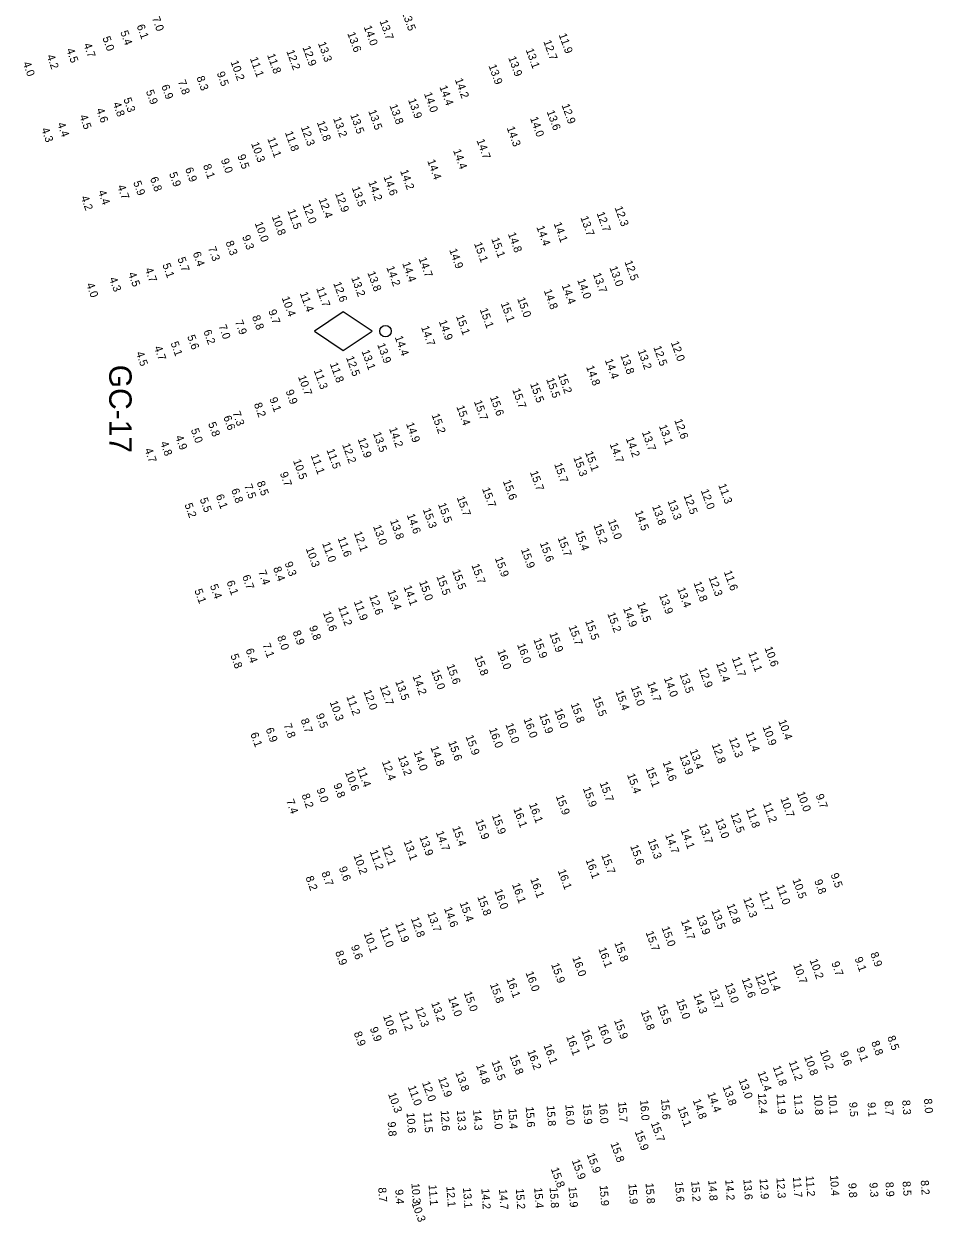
# Model space of a CAD drawing. Extents: x 815385 to 820851, y 582449 to 604245.
# Drawn here: x 820211 to 820779, y 590963 to 591711 of the extents above; entities that cross this region are included whole.
import ezdxf

# ---------------------------------------------------------------- set-up
doc = ezdxf.new("R2010")
doc.units = 0
for name, color, linetype in [('V-CHAN-AIDS', 7, 'Continuous'), ('V-TOPO-SOUN-021309', 7, 'Continuous'), ('V-TOPO-SOUN-112008', 7, 'Continuous'), ('V-TOPO-SOUN-EXCSS', 7, 'Continuous')]:
    doc.layers.add(name, color=color, linetype=linetype)

msp = doc.modelspace()

# ---------------------------------------------------------------- linework, layer by layer
at = {"layer": 'V-CHAN-AIDS'}
msp.add_lwpolyline([(820428.13, 591519.27), (820410.13, 591531.27), (820392.13, 591519.27), (820410.13, 591507.27)], close=True, dxfattribs=at)
msp.add_circle((820436.53, 591519.27), 3.6, dxfattribs=at)

# ---------------------------------------------------------------- texts
msp.add_text('GC-17', height=14, rotation=270, dxfattribs=at).set_placement((820263.84, 591498.29))
at = {"layer": 'V-TOPO-SOUN-021309'}
for s, rotation, p in [('12.0 ', 289.902, (820614.81, 591512.17)), ('13.8 ', 289.902, (820583.24, 591504.04)), ('13.2 ', 289.902, (820594.08, 591507.01)), ('12.5 ', 289.902, (820603.84, 591509.24)), ('14.8 ', 289.902, (820561.86, 591496.92)), ('14.4 ', 289.902, (820573.54, 591501.13)), ('15.5 ', 289.902, (820536.88, 591489.21)), ('15.2 ', 289.902, (820544.23, 591491.95)), ('15.7 ', 289.902, (820515.7, 591482.65)), ('15.5 ', 289.902, (820526.8, 591486.31)), ('15.7 ', 289.902, (820491.72, 591475.26)), ('15.6 ', 289.902, (820501.73, 591478.04)), ('15.2 ', 289.902, (820465.28, 591466.89)), ('15.4 ', 289.902, (820480.77, 591472.03)), ('14.9 ', 289.902, (820449.3, 591461.4)), ('13.1 ', 289.902, (820607.38, 591459.95)), ('12.6 ', 289.902, (820616.96, 591463.57)), ('12.9 ', 289.902, (820419.06, 591451.8)), ('13.5 ', 289.902, (820428.66, 591455.39)), ('14.2 ', 289.902, (820438.68, 591458.34)), ('14.2 ', 289.902, (820586.66, 591452.22)), ('13.7 ', 289.902, (820596.73, 591456.09)), ('11.5 ', 289.902, (820399.59, 591444.97)), ('12.2 ', 289.902, (820409.36, 591448.31)), ('14.7 ', 289.902, (820576.6, 591448.68)), ('10.5 ', 289.902, (820378.66, 591438.31)), ('11.1 ', 289.902, (820389.7, 591441.61)), ('15.3 ', 289.902, (820553.86, 591440.22)), ('15.1 ', 289.902, (820561.19, 591443.41)), ('9.7', 289.902, (820370.41, 591430.4)), ('15.7 ', 289.902, (820526.75, 591431.15)), ('15.7 ', 289.902, (820541.86, 591436.16)), ('7.5', 289.902, (820348.12, 591422.78)), ('8.5', 289.902, (820355.98, 591424.68)), ('15.6 ', 289.902, (820509.83, 591425.46)), ('11.3 ', 289.902, (820644.45, 591423.09)), ('5.5', 289.902, (820320.34, 591414.25)), ('6.1', 289.902, (820330.36, 591416.43)), ('6.8', 289.902, (820339.95, 591420.05)), ('15.7 ', 289.902, (820480.99, 591415.29)), ('15.7 ', 289.902, (820496.81, 591420.78)), ('12.5 ', 289.902, (820622.75, 591416.52)), ('12.0 ', 289.902, (820633.52, 591419.66)), ('5.2', 289.902, (820310.81, 591410.89)), ('15.3 ', 289.902, (820459.77, 591407.77)), ('15.5 ', 289.902, (820469.28, 591411.11)), ('14.5 ', 289.902, (820592.34, 591406.28)), ('13.8 ', 289.902, (820603.09, 591409.78)), ('13.3 ', 289.902, (820612.76, 591413.04)), ('13.8 ', 289.902, (820439.26, 591400.79)), ('14.6 ', 289.902, (820449.76, 591404.34)), ('15.0 ', 289.902, (820575.49, 591400.81)), ('12.1 ', 289.902, (820416.71, 591393.27)), ('13.0 ', 289.902, (820428.7, 591397.25)), ('15.4 ', 289.902, (820555.04, 591393.8)), ('15.2 ', 289.902, (820566.46, 591398)), ('11.0 ', 289.902, (820396.84, 591386.62)), ('11.6 ', 289.902, (820406.54, 591389.9)), ('15.6 ', 289.902, (820532.93, 591386.81)), ('15.7 ', 289.902, (820544.05, 591390.1)), ('10.3 ', 289.902, (820386.6, 591383.39)), ('15.9 ', 289.902, (820504.81, 591377.37)), ('15.9 ', 289.902, (820521.1, 591382.79)), ('7.4', 289.902, (820356.87, 591368.94)), ('8.4', 289.902, (820366.21, 591371.16)), ('9.3', 289.902, (820373.37, 591374.32)), ('15.5 ', 289.902, (820478.1, 591369.54)), ('15.7 ', 289.902, (820490.17, 591373.01)), ('11.6 ', 289.902, (820647.94, 591368.83)), ('6.1', 289.902, (820337.06, 591362.53)), ('6.7', 289.902, (820346.86, 591366.02)), ('15.0 ', 289.902, (820457.42, 591362.57)), ('15.5 ', 289.902, (820468.28, 591365.99)), ('12.8 ', 289.902, (820628.99, 591361.93)), ('12.3 ', 289.902, (820638.41, 591365.29)), ('5.1', 289.902, (820316.98, 591357.3)), ('5.4', 289.902, (820326.69, 591360.21)), ('13.4 ', 289.902, (820437.67, 591356.79)), ('14.1 ', 289.902, (820447.76, 591359.48)), ('13.9 ', 289.902, (820607.47, 591354.19)), ('13.4 ', 289.902, (820618.8, 591358.24)), ('11.2 ', 289.902, (820406.87, 591346.76)), ('11.9 ', 289.902, (820416.63, 591350.17)), ('12.6 ', 289.902, (820426.23, 591353.68)), ('14.5 ', 289.902, (820593.67, 591349.05)), ('10.6 ', 289.902, (820397.35, 591343.34)), ('15.2 ', 289.902, (820575.11, 591342.73)), ('14.9 ', 289.902, (820584.96, 591346.04)), ('8.9', 289.902, (820378.42, 591331.33)), ('9.8', 289.902, (820388.67, 591334.32)), ('15.7 ', 289.902, (820550.93, 591334.6)), ('15.5 ', 289.902, (820561.25, 591337.98)), ('7.1', 289.902, (820359.52, 591323.38)), ('8.0', 289.902, (820368.7, 591328.16)), ('15.9 ', 289.902, (820528.88, 591326.55)), ('15.9 ', 289.902, (820538.83, 591330.29)), ('5.8', 289.902, (820339.49, 591316.66)), ('6.4', 289.902, (820348.99, 591320.09)), ('16.0 ', 289.902, (820506.32, 591319.51)), ('16.0 ', 289.902, (820518.72, 591323.28)), ('11.1 ', 289.902, (820663.22, 591318.15)), ('10.6 ', 289.902, (820673.37, 591321.32)), ('15.6 ', 289.902, (820474.59, 591310.29)), ('15.8 ', 289.902, (820492.03, 591315.72)), ('12.4 ', 289.902, (820643.08, 591311.72)), ('11.7 ', 289.902, (820652.93, 591314.93)), ('14.2 ', 289.902, (820453.36, 591303.6)), ('15.0 ', 289.902, (820464.98, 591306.99)), ('14.0 ', 289.902, (820610.48, 591302.34)), ('13.5 ', 289.902, (820620.25, 591304.74)), ('12.9 ', 289.902, (820632.26, 591308.13)), ('12.0 ', 289.902, (820422.67, 591294.24)), ('12.7 ', 289.902, (820432.78, 591297.15)), ('13.5 ', 289.902, (820442.54, 591300.28)), ('15.4 ', 289.902, (820580.17, 591293.96)), ('15.0 ', 289.902, (820589.84, 591296.76)), ('14.7 ', 289.902, (820599.96, 591299.39)), ('10.3 ', 289.902, (820401.56, 591287.41)), ('11.2 ', 289.902, (820411.96, 591290.89)), ('15.5 ', 289.902, (820565.91, 591290.23)), ('9.5', 289.902, (820392.93, 591279.44)), ('15.9 ', 289.902, (820532.5, 591279.43)), ('16.0 ', 289.902, (820541.96, 591282.68)), ('15.8 ', 289.902, (820552.22, 591286.21)), ('7.8', 289.902, (820372.74, 591273.19)), ('8.7', 289.902, (820383.42, 591276.33)), ('16.0 ', 289.902, (820511.4, 591273.47)), ('16.0 ', 289.902, (820522.71, 591276.78)), ('10.9 ', 289.902, (820672.13, 591271.94)), ('10.4 ', 289.902, (820681.98, 591275.63)), ('6.1', 289.902, (820351.95, 591267.61)), ('6.9', 289.902, (820361.52, 591270.58)), ('15.9 ', 289.902, (820486.5, 591266.03)), ('16.0 ', 289.902, (820501.15, 591270.52)), ('12.3 ', 289.902, (820651.15, 591264.51)), ('11.4 ', 289.902, (820661.59, 591268.13)), ('14.8 ', 289.902, (820464.55, 591259.11)), ('15.6 ', 289.902, (820475.6, 591262.47)), ('13.4 ', 289.902, (820626.55, 591257.2)), ('12.8 ', 289.902, (820640.4, 591260.77)), ('12.4 ', 289.902, (820434.17, 591250.17)), ('13.2 ', 289.902, (820444.21, 591253.21)), ('14.0 ', 289.902, (820454.03, 591256.25)), ('14.6 ', 289.902, (820609.67, 591249.75)), ('13.9 ', 289.902, (820620.17, 591253.77)), ('10.6 ', 289.902, (820411.17, 591243.58)), ('11.4 ', 289.902, (820418.61, 591246.09)), ('15.4 ', 289.902, (820587.43, 591242.03)), ('15.1 ', 289.902, (820599.15, 591246.02)), ('9.8', 289.902, (820403.85, 591235.83)), ('15.7 ', 289.902, (820570.31, 591236.89)), ('8.2', 289.902, (820383.98, 591229.37)), ('9.0', 289.902, (820393.34, 591232.89)), ('15.9 ', 289.902, (820542.93, 591228.65)), ('15.9 ', 289.902, (820559.81, 591233.55)), ('10.7 ', 289.902, (820683.29, 591227.14)), ('10.0 ', 289.902, (820693.62, 591230.68)), ('9.7', 289.902, (820705.31, 591229.14)), ('7.4', 289.902, (820374.36, 591225.83)), ('16.1 ', 289.902, (820516.33, 591220.72)), ('16.1 ', 289.902, (820526.13, 591223.64)), ('11.8 ', 289.902, (820661.76, 591220.52)), ('11.2 ', 289.902, (820672.39, 591223.89)), ('15.9 ', 289.902, (820492.58, 591213.33)), ('15.9 ', 289.902, (820502.98, 591216.56)), ('13.0 ', 289.902, (820642.58, 591213.96)), ('12.5 ', 289.902, (820652.09, 591217.46)), ('14.7 ', 289.902, (820467.93, 591206.09)), ('15.4 ', 289.902, (820478.16, 591209.07)), ('14.7 ', 289.902, (820611.23, 591204.42)), ('14.1 ', 289.902, (820620.98, 591207.47)), ('13.7 ', 289.902, (820632.33, 591210.65)), ('12.1 ', 289.902, (820434.25, 591197.15)), ('13.1 ', 289.902, (820447.75, 591200.28)), ('13.9 ', 289.902, (820457.64, 591203.09)), ('15.6 ', 289.902, (820589.42, 591197.43)), ('15.3 ', 289.902, (820600.38, 591201.12)), ('10.2 ', 289.902, (820416.4, 591191.54)), ('11.2 ', 289.902, (820426.59, 591194.24)), ('15.7 ', 289.902, (820571.33, 591191.75)), ('9.6', 289.902, (820407.3, 591183.79)), ('16.1 ', 289.902, (820544.12, 591182.07)), ('16.1 ', 289.902, (820561.57, 591188.81)), ('8.2', 289.902, (820386.48, 591177.89)), ('8.7', 289.902, (820396.39, 591180.79)), ('16.1 ', 289.902, (820526.94, 591176.82)), ('10.5 ', 289.902, (820690.85, 591176.34)), ('9.8', 289.902, (820704.45, 591175.69)), ('9.5', 289.902, (820714.68, 591179.65)), ('16.0 ', 289.902, (820504.47, 591169.72)), ('16.1 ', 289.902, (820515.54, 591173.49)), ('11.7 ', 289.902, (820669.96, 591168.47)), ('11.0 ', 289.902, (820680.69, 591172.55)), ('15.4 ', 289.902, (820482.79, 591161.91)), ('15.8 ', 289.902, (820493.81, 591165.71)), ('12.8 ', 289.902, (820649.71, 591160.64)), ('12.3 ', 289.902, (820660.07, 591164.51)), ('12.8 ', 289.902, (820452.33, 591152.18)), ('13.7 ', 289.902, (820462.56, 591155.52)), ('14.6 ', 289.902, (820473.03, 591158.49)), ('13.9 ', 289.902, (820630.76, 591153.73)), ('13.5 ', 289.902, (820640.21, 591157.14)), ('11.0 ', 289.902, (820432.86, 591145.92)), ('11.9 ', 289.902, (820442.53, 591149)), ('15.0 ', 289.902, (820609.01, 591146.41)), ('14.7 ', 289.902, (820621.13, 591150.67)), ('10.1 ', 289.902, (820422.83, 591142.77)), ('15.8 ', 289.902, (820579.52, 591136.93)), ('15.7 ', 289.902, (820599.05, 591143.51)), ('8.9', 289.902, (820404.98, 591131.23)), ('9.6', 289.902, (820414.83, 591134.81)), ('16.1 ', 289.902, (820569.5, 591133.28)), ('8.9', 289.902, (820739.45, 591130.26)), ('15.9 ', 289.902, (820539.96, 591123.55)), ('16.0 ', 289.902, (820553.2, 591127.7)), ('10.7 ', 289.902, (820691.31, 591123.14)), ('10.2 ', 289.902, (820701.55, 591126.12)), ('9.7', 289.902, (820715.13, 591124.45)), ('9.1', 289.902, (820729.66, 591127.27)), ('16.1 ', 289.902, (820512.01, 591114.4)), ('16.0 ', 289.902, (820524, 591118.33)), ('12.6 ', 289.902, (820659.09, 591114.31)), ('12.0 ', 289.902, (820667.49, 591116.41)), ('11.4 ', 289.902, (820674.63, 591118.62)), ('15.8 ', 289.902, (820501.71, 591111)), ('13.7 ', 289.902, (820638.7, 591107.31)), ('13.0 ', 289.902, (820648.55, 591111.12)), ('13.2 ', 289.902, (820464.99, 591099.34)), ('14.0 ', 289.902, (820475.55, 591102.64)), ('15.0 ', 289.902, (820485.38, 591105.78)), ('15.0 ', 289.902, (820618.15, 591101.08)), ('14.3 ', 289.902, (820628.87, 591104.46)), ('11.2 ', 289.902, (820444.84, 591093.72)), ('12.3 ', 289.902, (820454.91, 591096.09)), ('15.8 ', 289.902, (820596.02, 591094.08)), ('15.5 ', 289.902, (820606.38, 591097.79)), ('10.6 ', 289.902, (820434.91, 591091.22)), ('16.0 ', 289.902, (820569.23, 591085.4)), ('15.9 ', 289.902, (820579.3, 591088.53)), ('8.9', 289.902, (820416.62, 591080.69)), ('9.9', 289.902, (820426.66, 591083.5)), ('16.1 ', 289.902, (820549.37, 591078.42)), ('16.1 ', 289.902, (820558.91, 591082.06)), ('8.5', 289.902, (820750.08, 591078.06)), ('16.2 ', 289.902, (820525.05, 591069.35)), ('16.1 ', 289.902, (820535.27, 591072.96)), ('10.2 ', 289.902, (820707.91, 591069.37)), ('9.1', 289.902, (820730.77, 591071.13)), ('8.8', 289.902, (820740.05, 591074.89)), ('15.5 ', 289.902, (820502.7, 591062.69)), ('15.8 ', 289.902, (820513.95, 591066.32)), ('11.2 ', 289.902, (820688.48, 591062.57)), ('10.8 ', 289.902, (820698.08, 591065.82)), ('9.6', 289.902, (820720.49, 591068.31)), ('13.8 ', 289.902, (820480.11, 591055.87)), ('14.8 ', 289.902, (820493.05, 591060.45)), ('12.4 ', 289.902, (820669, 591055.95)), ('11.8 ', 289.902, (820678.58, 591059.4)), ('11.0 ', 289.902, (820450.44, 591046.98)), ('12.0 ', 289.902, (820459.27, 591049.58)), ('12.9 ', 289.902, (820469.34, 591052.29)), ('13.8 ', 289.902, (820647.15, 591047.02)), ('13.0 ', 289.902, (820657.19, 591051.29)), ('10.3 ', 289.902, (820438.06, 591042.51)), ('14.4 ', 289.902, (820637.58, 591042.81)), ('12.4 ', 274.208, (820669.32, 591042.89)), ('11.9 ', 274.208, (820680.98, 591042.63)), ('11.3 ', 274.208, (820691.76, 591042.36)), ('10.8 ', 274.208, (820704.3, 591042.24)), ('10.1 ', 274.208, (820713.36, 591042.25)), ('15.0 ', 274.208, (820503.93, 591033.27)), ('15.4 ', 274.208, (820513.32, 591033.46)), ('15.6 ', 274.208, (820524.15, 591034.53)), ('15.8 ', 274.208, (820537.23, 591035.24)), ('16.0 ', 274.208, (820548.92, 591035.91)), ('15.9 ', 274.208, (820559.91, 591036.34)), ('16.0 ', 274.208, (820569.99, 591036.86)), ('15.7 ', 274.208, (820581.91, 591037.68)), ('16.0 ', 274.208, (820595.67, 591038.77)), ('15.6 ', 274.208, (820608.74, 591039.34)), ('15.1 ', 289.902, (820618.98, 591033.8)), ('14.8 ', 289.902, (820628.5, 591038.59)), ('9.5', 274.208, (820726.29, 591037.37)), ('9.1', 274.208, (820737.8, 591037.32)), ('8.7', 274.208, (820748.51, 591038.24)), ('8.3', 274.208, (820759.46, 591038.65)), ('8.0', 274.208, (820773.1, 591039.59)), ('10.6 ', 274.208, (820449.67, 591030.85)), ('11.5 ', 274.208, (820460.3, 591031.15)), ('12.6 ', 274.208, (820471, 591032.21)), ('13.3 ', 274.208, (820481.12, 591032.4)), ('14.3 ', 274.208, (820491.27, 591032.61)), ('9.8', 274.208, (820437.85, 591025.15)), ('15.9 ', 289.902, (820592.25, 591018.97)), ('15.7 ', 289.902, (820602.26, 591024.35)), ('15.8 ', 289.902, (820577.05, 591011.56)), ('15.9 ', 289.902, (820562.29, 591004.78)), ('15.8 ', 289.902, (820539.79, 590995.74)), ('15.9 ', 289.902, (820552.89, 591000.84)), ('14.8 ', 274.208, (820638.24, 590988.63)), ('14.2 ', 274.208, (820648.88, 590988.9)), ('13.6 ', 274.208, (820660.18, 590989.22)), ('12.9 ', 274.208, (820670.33, 590989.6)), ('12.3 ', 274.208, (820680.86, 590990.17)), ('11.7 ', 274.208, (820691.16, 590990.65)), ('11.2 ', 274.208, (820699.2, 590991.32)), ('10.4 ', 274.208, (820714.37, 590991.66)), ('8.5', 274.208, (820759.67, 590987.94)), ('8.2', 274.208, (820771.04, 590988.57)), ('8.7', 274.208, (820431.95, 590984.05)), ('9.4', 274.208, (820442.57, 590982.83)), ('10.3 ', 274.208, (820452.71, 590986.77)), ('11.1 ', 274.208, (820463.46, 590985.71)), ('12.1 ', 274.208, (820474.54, 590984.75)), ('13.1 ', 274.208, (820484.93, 590983.98)), ('14.2 ', 274.208, (820496.41, 590983.38)), ('14.7 ', 274.208, (820507.45, 590983.04)), ('15.2 ', 274.208, (820517.98, 590983.33)), ('15.4 ', 274.208, (820529.47, 590983.93)), ('15.8 ', 274.208, (820539.09, 590984.06)), ('15.9 ', 274.208, (820550.92, 590984.47)), ('15.9 ', 274.208, (820570.37, 590985.41)), ('15.9 ', 274.208, (820588.34, 590986.45)), ('15.8 ', 274.208, (820599.08, 590986.84)), ('15.6 ', 274.208, (820617.45, 590987.79)), ('15.2 ', 274.208, (820627.6, 590988.04)), ('9.8', 274.208, (820725.78, 590986.86)), ('9.3', 274.208, (820738.98, 590987.14)), ('8.9', 274.208, (820749, 590987.47))]:
    msp.add_text(s, height=5, rotation=rotation, dxfattribs=at).set_placement(p)
at = {"layer": 'V-TOPO-SOUN-112008'}
for s, p in [('7.0', (820290.48, 591714.95)), ('13.5 ', (820446.61, 591718.68)), ('5.4', (820270.66, 591706.2)), ('6.1', (820280.91, 591710.06)), ('14.0 ', (820422.86, 591709.42)), ('13.7 ', (820432.74, 591713.02)), ('5.0', (820259.51, 591702.56)), ('13.3 ', (820394.25, 591699.2)), ('13.6 ', (820412.59, 591705.31)), ('12.7 ', (820535.12, 591700.3)), ('11.9 ', (820544.72, 591704.51)), ('4.2', (820224.68, 591691.23)), ('4.5', (820236.94, 591695.16)), ('4.7', (820247.68, 591698.4)), ('11.8 ', (820362.43, 591691.86)), ('12.2 ', (820374.48, 591694.2)), ('12.9 ', (820384.57, 591696.63)), ('13.1 ', (820524.11, 591695.11)), ('4.0', (820209.74, 591686.75)), ('10.2 ', (820339.59, 591687.54)), ('11.1 ', (820351.7, 591689.71)), ('13.9 ', (820500.84, 591685.13)), ('13.9 ', (820513.17, 591690.18)), ('7.8', (820306.65, 591675.32)), ('8.3', (820318.31, 591677.83)), ('9.5', (820330.99, 591680.58)), ('14.2 ', (820479.82, 591676.46)), ('5.9', (820286.68, 591669.17)), ('6.9', (820296.3, 591672.43)), ('14.4 ', (820470.14, 591671.96)), ('4.8', (820266.01, 591661.53)), ('5.3', (820272.61, 591664.26)), ('13.9 ', (820450.56, 591663.83)), ('14.0 ', (820460.5, 591667.69)), ('4.6', (820255.6, 591657.77)), ('13.5 ', (820414.41, 591654.33)), ('13.5 ', (820425.68, 591656.75)), ('13.8 ', (820438.94, 591660.23)), ('13.6 ', (820537.19, 591656.48)), ('12.9 ', (820546.51, 591660.51)), ('4.4', (820231.25, 591648.84)), ('4.5', (820245.13, 591653.65)), ('12.3 ', (820383.53, 591646.74)), ('12.8 ', (820393.55, 591649.74)), ('13.2 ', (820403.72, 591652.14)), ('14.3 ', (820512.2, 591646.35)), ('14.0 ', (820526.8, 591652.38)), ('4.3', (820221.29, 591645.52)), ('11.1 ', (820362.61, 591639.56)), ('11.8 ', (820373.59, 591643.39)), ('14.7 ', (820493.36, 591638.5)), ('10.3 ', (820352.42, 591636.52)), ('14.4 ', (820478.7, 591632.19)), ('9.0', (820333.55, 591626.24)), ('9.5', (820343.88, 591628.82)), ('14.4 ', (820462.56, 591625.69)), ('5.9', (820301.17, 591617.73)), ('6.9', (820311.17, 591620.7)), ('8.1', (820322.41, 591622.76)), ('14.2 ', (820445.63, 591619.33)), ('4.7', (820268.82, 591609.81)), ('5.9', (820278.74, 591612.27)), ('6.8', (820289.25, 591614.75)), ('13.5 ', (820415.4, 591608.85)), ('14.2 ', (820425.68, 591612.43)), ('14.6 ', (820435.21, 591615.71)), ('4.2', (820246, 591602.92)), ('4.4', (820256.75, 591606.49)), ('12.4 ', (820394.65, 591601.63)), ('12.9 ', (820404.94, 591605.3)), ('11.5 ', (820375.17, 591594.63)), ('12.0 ', (820384.59, 591598.15)), ('12.3 ', (820579.66, 591596.48)), ('10.0 ', (820354.72, 591586.74)), ('10.8 ', (820365.38, 591590.83)), ('14.1 ', (820541.57, 591586.5)), ('13.7 ', (820558.26, 591590.3)), ('12.7 ', (820568.42, 591592.99)), ('9.3', (820346.82, 591578.37)), ('14.8 ', (820512.98, 591580.15)), ('14.4 ', (820530.78, 591584.32)), ('7.3', (820325.52, 591571.26)), ('8.3', (820336.48, 591574.84)), ('15.1 ', (820491.79, 591573.99)), ('15.1 ', (820502.57, 591576.9)), ('5.7', (820306.41, 591564.59)), ('6.4', (820315.96, 591567.97)), ('14.7 ', (820457.15, 591564.6)), ('14.9 ', (820476.27, 591570.01)), ('4.7', (820286.07, 591558.03)), ('5.1', (820297, 591560.78)), ('14.2 ', (820437, 591559.09)), ('14.4 ', (820446.88, 591561.69)), ('13.0 ', (820576.41, 591558.97)), ('12.5 ', (820585.84, 591562.58)), ('4.3', (820263.74, 591552.11)), ('4.5', (820275.59, 591555.24)), ('12.6 ', (820403.81, 591549.18)), ('13.2 ', (820415.03, 591552.52)), ('13.8 ', (820425.14, 591555.79)), ('14.0 ', (820556.29, 591551.16)), ('13.7 ', (820566.15, 591554.89)), ('4.0', (820249.4, 591548.53)), ('11.4 ', (820382.88, 591542.99)), ('11.7 ', (820393.13, 591546.05)), ('14.8 ', (820535.41, 591544.59)), ('14.4 ', (820546.6, 591547.86)), ('10.4 ', (820371.54, 591540.11)), ('15.1 ', (820508.47, 591536.56)), ('15.0 ', (820518.77, 591539.59)), ('8.8', (820353.01, 591528.29)), ('9.7', (820363.19, 591531.86)), ('15.1 ', (820480.53, 591528.6)), ('15.1 ', (820495.35, 591532.82)), ('6.2', (820322.63, 591519.21)), ('7.0', (820332.07, 591522.5)), ('7.9', (820342.36, 591525.27)), ('14.7 ', (820458.66, 591521.75)), ('14.9 ', (820469.77, 591525.31)), ('5.1', (820302.09, 591511.87)), ('5.6', (820312.49, 591516.01)), ('14.4 ', (820442.26, 591515.52)), ('4.5', (820280.44, 591505.64)), ('4.7', (820291.8, 591509.15)), ('13.1 ', (820421.49, 591506.74)), ('13.9 ', (820431.26, 591510.9)), ('11.8 ', (820401.67, 591498.83)), ('12.5 ', (820411.76, 591502.81)), ('10.7 ', (820381.81, 591490.76)), ('11.3 ', (820391.6, 591494.71)), ('9.9', (820374.02, 591481.79)), ('8.2', (820354.18, 591473.67)), ('9.1', (820363.83, 591477.03)), ('7.3', (820340.79, 591468.31)), ('5.8', (820325.52, 591461.55)), ('6.6', (820335.08, 591465.59)), ('4.9', (820305.03, 591453.27)), ('5.0', (820314.78, 591457.58)), ('4.7', (820285.85, 591445.28)), ('4.8', (820295.65, 591449.52))]:
    msp.add_text(s, height=5, rotation=289.902, dxfattribs=at).set_placement(p)
at = {"layer": 'V-TOPO-SOUN-EXCSS'}
msp.add_text('10.3 ', height=5, rotation=289.902, dxfattribs=at).set_placement((820452.8, 590974.28))

doc.saveas('drawing.dxf')
